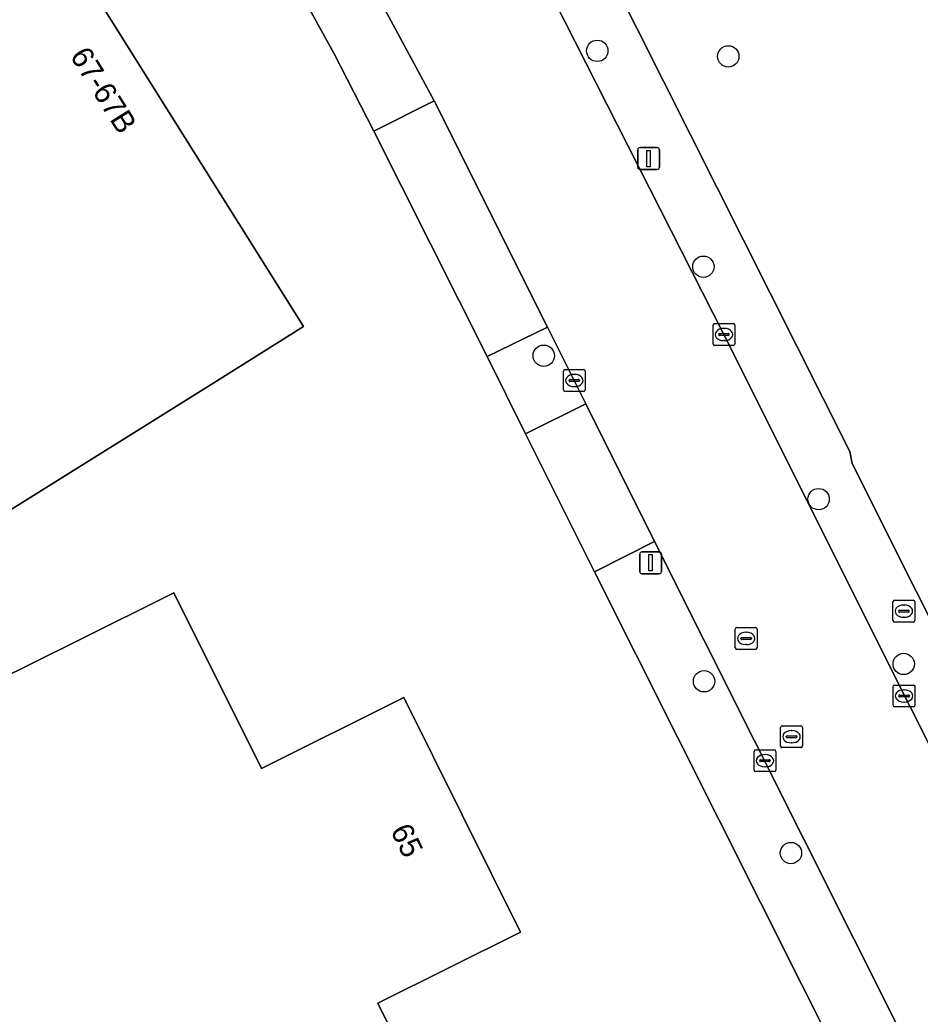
# Model space of a CAD drawing. Extents: x 158455 to 159797, y 387218 to 388672.
# Drawn here: x 158895.54 to 158936.77, y 387610.64 to 387656.15 of the extents above; entities that cross this region are included whole.
import ezdxf

# ---------------------------------------------------------------- set-up
doc = ezdxf.new("R2010")
doc.units = 0
for name, color, linetype in [('IMGEO_Boom', 7, 'Continuous'), ('IMGEO_Brandkraan', 7, 'Continuous'), ('IMGEO_Erf', 7, 'Continuous'), ('IMGEO_Groenvoorziening', 7, 'Continuous'), ('IMGEO_Kolk', 7, 'Continuous'), ('IMGEO_Lichtmast', 7, 'Continuous'), ('IMGEO_Pand', 7, 'Continuous'), ('IMGEO_Pand_nummerreeks', 7, 'Continuous'), ('IMGEO_Rijbaan_lokaal_gesloten', 7, 'Continuous'), ('IMGEO_Rioolput', 7, 'Continuous'), ('IMGEO_Voetpad_open', 7, 'Continuous')]:
    doc.layers.add(name, color=color, linetype=linetype)

msp = doc.modelspace()

# ---------------------------------------------------------------- linework, layer by layer
at = {"layer": 'IMGEO_Boom'}
for centre in [(158921.984, 387654.736), (158927.986, 387654.482), (158926.848, 387644.852), (158919.537, 387640.778), (158932.124, 387634.213), (158936.021, 387626.668), (158926.88, 387625.877), (158930.855, 387618.013)]:
    msp.add_circle(centre, 0.489, dxfattribs=at)
at = {"layer": 'IMGEO_Brandkraan'}
for p, q in [((158935.605, 387629.586), (158936.457, 387629.586)), ((158935.53, 387628.66), (158935.53, 387629.512)), ((158935.789, 387629.08), (158935.789, 387629.092)), ((158935.832, 387629.129), (158936.23, 387629.129)), ((158936.018, 387629.366), (158936.043, 387629.366)), ((158936.273, 387629.092), (158936.273, 387629.08)), ((158936.531, 387629.512), (158936.531, 387628.66)), ((158936.227, 387629.043), (158935.829, 387629.043)), ((158936.041, 387628.806), (158936.016, 387628.806)), ((158936.457, 387628.586), (158935.605, 387628.586))]:
    msp.add_line(p, q, dxfattribs=at)
for points in [[(158935.605, 387629.586), (158936.457, 387629.586)], [(158935.53, 387628.66), (158935.53, 387629.512)], [(158936.531, 387629.512), (158936.531, 387628.66)], [(158936.457, 387628.586), (158935.605, 387628.586)]]:
    msp.add_lwpolyline(points, dxfattribs=at)
for centre, radius, start, end in [((158935.607, 387629.51), 0.0765, 91.552, 178.448), ((158935.607, 387629.51), 0.0765, 91.552, 178.448), ((158936.455, 387629.51), 0.0765, 1.552, 88.448), ((158936.455, 387629.51), 0.0765, 1.552, 88.448), ((158935.829, 387629.089), 0.0403, 85.8775, 175.7526), ((158935.826, 387629.079), 0.0366, 178.938, 274.7102), ((158936.23, 387629.086), 0.043, 264.8664, 352.4533), ((158936.234, 387629.091), 0.0386, 1.7309, 96.639), ((158935.607, 387628.662), 0.0765, 181.552, 268.448), ((158935.607, 387628.662), 0.0765, 181.552, 268.448), ((158936.455, 387628.662), 0.0765, 271.552, 358.448), ((158936.455, 387628.662), 0.0765, 271.552, 358.448)]:
    msp.add_arc(centre, radius, start, end, dxfattribs=at)
for centre, major_axis, ratio, start_param, end_param in [((158936.017, 387629.086), (-0.387, 0.002), 0.722429, 4.712389, 7.853982), ((158936.042, 387629.086), (-0.39, 0.002), 0.717154, 1.570796, 4.712389)]:
    msp.add_ellipse(centre, major_axis=major_axis, ratio=ratio, start_param=start_param, end_param=end_param, dxfattribs=at)
at = {"layer": 'IMGEO_Erf'}
for points in [[(158943.323, 387588.149), (158935.963, 387602.773), (158933.26, 387608.176), (158921.856, 387630.891), (158918.695, 387637.196), (158916.94, 387640.737), (158911.753, 387651.052), (158909.925, 387654.635), (158906.951, 387660.034), (158903.404, 387666.016), (158897.586, 387674.782)], [(158895.119, 387663.494), (158908.535, 387642.117), (158904.295, 387639.469), (158885.82, 387627.929), (158888.801, 387623.081), (158898.121, 387627.704), (158902.597, 387629.931), (158906.604, 387621.885), (158913.12, 387625.134), (158918.477, 387614.393), (158911.935, 387611.134), (158915.862, 387603.234), (158911.387, 387601.004), (158897.995, 387594.33), (158886.575, 387615.835), (158883.635, 387620.442), (158869.854, 387642.432), (158867.642, 387645.962), (158864.987, 387650.199), (158869.238, 387652.895), (158867.621, 387655.417), (158878.047, 387661.941)]]:
    msp.add_lwpolyline(points, dxfattribs=at)
at = {"layer": 'IMGEO_Groenvoorziening'}
msp.add_lwpolyline([(158908.159, 387682.093), (158913.743, 387673.679), (158916.645, 387668.895), (158919.566, 387663.783), (158922.608, 387658.152), (158933.55, 387636.401), (158933.668, 387635.841), (158945.355, 387612.535), (158951.609, 387615.644), (158951.046, 387616.798), (158948.883, 387621.227), (158946.279, 387626.609), (158944.377, 387630.625), (159006.332, 387661.445), (159008.345, 387657.448), (159012.199, 387659.391)], dxfattribs=at)
at = {"layer": 'IMGEO_Kolk'}
for p, q in [((158927.288, 387641.325), (158927.288, 387642.177)), ((158927.363, 387642.251), (158928.215, 387642.251)), ((158927.776, 387642.031), (158927.801, 387642.031)), ((158928.289, 387642.177), (158928.289, 387641.325)), ((158927.547, 387641.745), (158927.547, 387641.757)), ((158927.985, 387641.708), (158927.587, 387641.708)), ((158927.59, 387641.794), (158927.988, 387641.794)), ((158927.799, 387641.471), (158927.774, 387641.471)), ((158928.031, 387641.757), (158928.031, 387641.745)), ((158928.215, 387641.251), (158927.363, 387641.251)), ((158920.434, 387639.217), (158920.434, 387640.069)), ((158920.509, 387640.143), (158921.361, 387640.143)), ((158921.435, 387640.069), (158921.435, 387639.217)), ((158920.693, 387639.637), (158920.693, 387639.649)), ((158921.131, 387639.6), (158920.733, 387639.6)), ((158920.736, 387639.686), (158921.134, 387639.686)), ((158920.922, 387639.923), (158920.947, 387639.923)), ((158921.177, 387639.649), (158921.177, 387639.637)), ((158921.361, 387639.143), (158920.509, 387639.143)), ((158920.945, 387639.363), (158920.92, 387639.363)), ((158935.538, 387624.778), (158935.538, 387625.63)), ((158935.613, 387625.704), (158936.465, 387625.704)), ((158936.026, 387625.484), (158936.051, 387625.484)), ((158936.539, 387625.63), (158936.539, 387624.778)), ((158935.797, 387625.198), (158935.797, 387625.21)), ((158936.235, 387625.161), (158935.837, 387625.161)), ((158935.84, 387625.247), (158936.238, 387625.247)), ((158936.281, 387625.21), (158936.281, 387625.198)), ((158936.465, 387624.704), (158935.613, 387624.704)), ((158936.049, 387624.924), (158936.024, 387624.924)), ((158929.242, 387622.739), (158930.094, 387622.739)), ((158929.167, 387621.813), (158929.167, 387622.665)), ((158929.426, 387622.233), (158929.426, 387622.245)), ((158929.469, 387622.282), (158929.867, 387622.282)), ((158929.655, 387622.519), (158929.68, 387622.519)), ((158929.91, 387622.245), (158929.91, 387622.233)), ((158930.168, 387622.665), (158930.168, 387621.813)), ((158929.864, 387622.196), (158929.466, 387622.196)), ((158929.678, 387621.959), (158929.653, 387621.959)), ((158930.094, 387621.739), (158929.242, 387621.739))]:
    msp.add_line(p, q, dxfattribs=at)
for points in [[(158927.288, 387641.325), (158927.288, 387642.177)], [(158927.363, 387642.251), (158928.215, 387642.251)], [(158928.289, 387642.177), (158928.289, 387641.325)], [(158928.215, 387641.251), (158927.363, 387641.251)], [(158920.434, 387639.217), (158920.434, 387640.069)], [(158920.509, 387640.143), (158921.361, 387640.143)], [(158921.435, 387640.069), (158921.435, 387639.217)], [(158921.361, 387639.143), (158920.509, 387639.143)], [(158935.538, 387624.778), (158935.538, 387625.63)], [(158935.613, 387625.704), (158936.465, 387625.704)], [(158936.539, 387625.63), (158936.539, 387624.778)], [(158936.465, 387624.704), (158935.613, 387624.704)], [(158929.242, 387622.739), (158930.094, 387622.739)], [(158929.167, 387621.813), (158929.167, 387622.665)], [(158930.168, 387622.665), (158930.168, 387621.813)], [(158930.094, 387621.739), (158929.242, 387621.739)]]:
    msp.add_lwpolyline(points, dxfattribs=at)
for centre, radius, start, end in [((158927.365, 387642.175), 0.0765, 91.552, 178.448), ((158927.365, 387642.175), 0.0765, 91.552, 178.448), ((158928.213, 387642.175), 0.0765, 1.552, 88.448), ((158928.213, 387642.175), 0.0765, 1.552, 88.448), ((158927.587, 387641.754), 0.0403, 85.8775, 175.7526), ((158927.584, 387641.744), 0.0366, 178.938, 274.7102), ((158927.988, 387641.751), 0.043, 264.8664, 352.4533), ((158927.992, 387641.756), 0.0386, 1.7309, 96.639), ((158927.365, 387641.327), 0.0765, 181.552, 268.448), ((158927.365, 387641.327), 0.0765, 181.552, 268.448), ((158928.213, 387641.327), 0.0765, 271.552, 358.448), ((158928.213, 387641.327), 0.0765, 271.552, 358.448), ((158920.511, 387640.067), 0.0765, 91.552, 178.448), ((158920.511, 387640.067), 0.0765, 91.552, 178.448), ((158921.359, 387640.067), 0.0765, 1.552, 88.448), ((158921.359, 387640.067), 0.0765, 1.552, 88.448), ((158920.733, 387639.646), 0.0403, 85.8775, 175.7526), ((158920.73, 387639.636), 0.0366, 178.938, 274.7102), ((158921.134, 387639.643), 0.043, 264.8664, 352.4533), ((158921.138, 387639.648), 0.0386, 1.7309, 96.639), ((158920.511, 387639.219), 0.0765, 181.552, 268.448), ((158920.511, 387639.219), 0.0765, 181.552, 268.448), ((158921.359, 387639.219), 0.0765, 271.552, 358.448), ((158921.359, 387639.219), 0.0765, 271.552, 358.448), ((158935.615, 387625.628), 0.0765, 91.552, 178.448), ((158935.615, 387625.628), 0.0765, 91.552, 178.448), ((158936.463, 387625.628), 0.0765, 1.552, 88.448), ((158936.463, 387625.628), 0.0765, 1.552, 88.448), ((158935.837, 387625.207), 0.0403, 85.8775, 175.7526), ((158935.834, 387625.197), 0.0366, 178.938, 274.7102), ((158936.238, 387625.204), 0.043, 264.8664, 352.4533), ((158936.242, 387625.209), 0.0386, 1.7309, 96.639), ((158935.615, 387624.78), 0.0765, 181.552, 268.448), ((158935.615, 387624.78), 0.0765, 181.552, 268.448), ((158936.463, 387624.78), 0.0765, 271.552, 358.448), ((158936.463, 387624.78), 0.0765, 271.552, 358.448), ((158929.244, 387622.663), 0.0765, 91.552, 178.448), ((158929.244, 387622.663), 0.0765, 91.552, 178.448), ((158930.092, 387622.663), 0.0765, 1.552, 88.448), ((158930.092, 387622.663), 0.0765, 1.552, 88.448), ((158929.466, 387622.242), 0.0403, 85.8775, 175.7526), ((158929.871, 387622.244), 0.0386, 1.7309, 96.639), ((158929.244, 387621.815), 0.0765, 181.552, 268.448), ((158929.244, 387621.815), 0.0765, 181.552, 268.448), ((158929.463, 387622.232), 0.0366, 178.938, 274.7102), ((158929.867, 387622.239), 0.043, 264.8664, 352.4533), ((158930.092, 387621.815), 0.0765, 271.552, 358.448), ((158930.092, 387621.815), 0.0765, 271.552, 358.448)]:
    msp.add_arc(centre, radius, start, end, dxfattribs=at)
for centre, major_axis, ratio, start_param, end_param in [((158927.775, 387641.751), (-0.387, 0.002), 0.722429, 4.712389, 7.853982), ((158927.8, 387641.751), (-0.39, 0.002), 0.717154, 1.570796, 4.712389), ((158920.921, 387639.643), (-0.387, 0.002), 0.722429, 4.712389, 7.853982), ((158920.946, 387639.643), (-0.39, 0.002), 0.717154, 1.570796, 4.712389), ((158936.025, 387625.204), (-0.387, 0.002), 0.722429, 4.712389, 7.853982), ((158936.05, 387625.204), (-0.39, 0.002), 0.717154, 1.570796, 4.712389), ((158929.654, 387622.239), (-0.387, 0.002), 0.722429, 4.712389, 7.853982), ((158929.679, 387622.239), (-0.39, 0.002), 0.717154, 1.570796, 4.712389)]:
    msp.add_ellipse(centre, major_axis=major_axis, ratio=ratio, start_param=start_param, end_param=end_param, dxfattribs=at)
at = {"layer": 'IMGEO_Lichtmast'}
for p, q in [((158923.844, 387649.406), (158923.844, 387650.206)), ((158923.844, 387650.206), (158923.844, 387649.406)), ((158923.944, 387650.306), (158924.734, 387650.306)), ((158924.734, 387650.306), (158923.944, 387650.306)), ((158924.834, 387650.206), (158924.834, 387649.406)), ((158924.834, 387649.406), (158924.834, 387650.206)), ((158924.734, 387649.306), (158923.944, 387649.306)), ((158923.944, 387649.306), (158924.734, 387649.306)), ((158923.931, 387630.9), (158923.931, 387631.7)), ((158923.931, 387631.7), (158923.931, 387630.9)), ((158924.031, 387631.8), (158924.821, 387631.8)), ((158924.821, 387631.8), (158924.031, 387631.8)), ((158924.921, 387631.7), (158924.921, 387630.9)), ((158924.921, 387630.9), (158924.921, 387631.7)), ((158924.821, 387630.8), (158924.031, 387630.8)), ((158924.031, 387630.8), (158924.821, 387630.8))]:
    msp.add_line(p, q, dxfattribs=at)
for points in [[(158924.264, 387650.181), (158924.414, 387650.181), (158924.414, 387649.431), (158924.264, 387649.431), (158924.264, 387650.181)], [(158924.351, 387631.675), (158924.501, 387631.675), (158924.501, 387630.925), (158924.351, 387630.925), (158924.351, 387631.675)]]:
    msp.add_lwpolyline(points, dxfattribs=at)
for centre, start, end in [((158923.944, 387650.206), 90, 180), ((158923.944, 387650.206), 90, 180), ((158924.734, 387650.206), 0, 90), ((158924.734, 387650.206), 360, 90), ((158923.944, 387649.406), 180, 270), ((158923.944, 387649.406), 180, 270), ((158924.734, 387649.406), 270, 0), ((158924.734, 387649.406), 270, 0), ((158924.031, 387631.7), 90, 180), ((158924.031, 387631.7), 90, 180), ((158924.821, 387631.7), 0, 90), ((158924.821, 387631.7), 360, 90), ((158924.031, 387630.9), 180, 270), ((158924.031, 387630.9), 180, 270), ((158924.821, 387630.9), 270, 0), ((158924.821, 387630.9), 270, 0)]:
    msp.add_arc(centre, 0.1, start, end, dxfattribs=at)
at = {"layer": 'IMGEO_Pand'}
for points in [[(158895.119, 387663.494), (158896.065, 387664.099), (158894.225, 387667.08), (158888.459, 387668.453), (158883.343, 387665.253), (158878.323, 387662.112), (158877.512, 387663.377), (158877.239, 387663.227), (158878.047, 387661.941), (158867.621, 387655.417), (158869.238, 387652.895), (158864.987, 387650.199), (158867.642, 387645.962), (158869.854, 387642.432), (158883.635, 387620.442), (158888.801, 387623.081), (158885.82, 387627.929), (158904.295, 387639.469), (158908.535, 387642.117)], [(158883.635, 387620.442), (158886.575, 387615.835), (158897.995, 387594.33), (158911.387, 387601.004), (158915.862, 387603.234), (158911.935, 387611.134), (158918.477, 387614.393), (158913.12, 387625.134), (158906.604, 387621.885), (158902.597, 387629.931), (158898.121, 387627.704), (158888.801, 387623.081)]]:
    msp.add_lwpolyline(points, close=True, dxfattribs=at)
at = {"layer": 'IMGEO_Rijbaan_lokaal_gesloten'}
for points in [[(158952.06, 387593.215), (158951.418, 387594.547), (158944.884, 387607.596), (158927.789, 387641.751), (158919.992, 387657.088), (158917.009, 387662.578), (158914.339, 387667.291), (158911.457, 387672.114), (158905.886, 387680.514)], [(158900.847, 387675.374), (158901.529, 387674.337), (158904.447, 387669.973), (158907.576, 387664.901), (158911.705, 387657.663), (158914.511, 387652.445), (158919.71, 387642.093), (158921.465, 387638.578), (158924.613, 387632.28), (158936.019, 387609.551), (158938.739, 387604.133), (158945.43, 387590.82), (158945.878, 387589.923)]]:
    msp.add_lwpolyline(points, dxfattribs=at)
at = {"layer": 'IMGEO_Rioolput'}
for p, q in [((158928.305, 387627.411), (158928.305, 387628.263)), ((158928.38, 387628.337), (158929.232, 387628.337)), ((158929.306, 387628.263), (158929.306, 387627.411)), ((158928.564, 387627.831), (158928.564, 387627.843)), ((158929.002, 387627.794), (158928.604, 387627.794)), ((158928.607, 387627.88), (158929.005, 387627.88)), ((158928.793, 387628.117), (158928.818, 387628.117)), ((158929.048, 387627.843), (158929.048, 387627.831)), ((158929.232, 387627.337), (158928.38, 387627.337)), ((158928.816, 387627.557), (158928.791, 387627.557)), ((158930.384, 387622.911), (158930.384, 387623.763)), ((158930.459, 387623.837), (158931.311, 387623.837)), ((158930.872, 387623.617), (158930.897, 387623.617)), ((158931.385, 387623.763), (158931.385, 387622.911)), ((158930.643, 387623.331), (158930.643, 387623.343)), ((158931.081, 387623.294), (158930.683, 387623.294)), ((158930.686, 387623.38), (158931.084, 387623.38)), ((158931.127, 387623.343), (158931.127, 387623.331)), ((158931.311, 387622.837), (158930.459, 387622.837)), ((158930.895, 387623.057), (158930.87, 387623.057))]:
    msp.add_line(p, q, dxfattribs=at)
for points in [[(158928.305, 387627.411), (158928.305, 387628.263)], [(158928.38, 387628.337), (158929.232, 387628.337)], [(158929.306, 387628.263), (158929.306, 387627.411)], [(158929.232, 387627.337), (158928.38, 387627.337)], [(158930.384, 387622.911), (158930.384, 387623.763)], [(158930.459, 387623.837), (158931.311, 387623.837)], [(158931.385, 387623.763), (158931.385, 387622.911)], [(158931.311, 387622.837), (158930.459, 387622.837)]]:
    msp.add_lwpolyline(points, dxfattribs=at)
for centre, radius, start, end in [((158928.382, 387628.261), 0.0765, 91.552, 178.448), ((158928.382, 387628.261), 0.0765, 91.552, 178.448), ((158929.23, 387628.261), 0.0765, 1.552, 88.448), ((158929.23, 387628.261), 0.0765, 1.552, 88.448), ((158928.604, 387627.84), 0.0403, 85.8775, 175.7526), ((158928.601, 387627.83), 0.0366, 178.938, 274.7102), ((158929.005, 387627.837), 0.043, 264.8664, 352.4533), ((158929.009, 387627.842), 0.0386, 1.7309, 96.639), ((158928.382, 387627.413), 0.0765, 181.552, 268.448), ((158928.382, 387627.413), 0.0765, 181.552, 268.448), ((158929.23, 387627.413), 0.0765, 271.552, 358.448), ((158929.23, 387627.413), 0.0765, 271.552, 358.448), ((158930.461, 387623.761), 0.0765, 91.552, 178.448), ((158930.461, 387623.761), 0.0765, 91.552, 178.448), ((158931.309, 387623.761), 0.0765, 1.552, 88.448), ((158931.309, 387623.761), 0.0765, 1.552, 88.448), ((158930.683, 387623.34), 0.0403, 85.8775, 175.7526), ((158930.68, 387623.33), 0.0366, 178.938, 274.7102), ((158931.084, 387623.337), 0.043, 264.8664, 352.4533), ((158931.088, 387623.342), 0.0386, 1.7309, 96.639), ((158930.461, 387622.913), 0.0765, 181.552, 268.448), ((158930.461, 387622.913), 0.0765, 181.552, 268.448), ((158931.309, 387622.913), 0.0765, 271.552, 358.448), ((158931.309, 387622.913), 0.0765, 271.552, 358.448)]:
    msp.add_arc(centre, radius, start, end, dxfattribs=at)
for centre, major_axis, ratio, start_param, end_param in [((158928.792, 387627.837), (-0.387, 0.002), 0.722429, 4.712389, 7.853982), ((158928.817, 387627.837), (-0.39, 0.002), 0.717154, 1.570796, 4.712389), ((158930.871, 387623.337), (-0.387, 0.002), 0.722429, 4.712389, 7.853982), ((158930.896, 387623.337), (-0.39, 0.002), 0.717154, 1.570796, 4.712389)]:
    msp.add_ellipse(centre, major_axis=major_axis, ratio=ratio, start_param=start_param, end_param=end_param, dxfattribs=at)
at = {"layer": 'IMGEO_Voetpad_open'}
for points in [[(158933.55, 387636.401), (158922.608, 387658.152), (158919.566, 387663.783), (158916.645, 387668.895), (158913.743, 387673.679), (158908.159, 387682.093)], [(158906.826, 387681.188), (158905.886, 387680.514), (158911.457, 387672.114), (158914.339, 387667.291), (158917.009, 387662.578), (158919.992, 387657.088), (158927.789, 387641.751), (158944.884, 387607.596), (158945.355, 387607.843), (158951.877, 387594.81), (158952.504, 387595.008), (158953.469, 387593.046)], [(158897.586, 387674.782), (158903.404, 387666.016), (158906.951, 387660.034), (158909.925, 387654.635), (158911.753, 387651.052), (158914.511, 387652.445), (158911.705, 387657.663)], [(158948.418, 387573.599), (158949.423, 387571.741), (158957.461, 387576.099), (158957.303, 387576.367), (158962.13, 387578.938), (158947.594, 387608.591), (158947.378, 387608.501), (158945.355, 387612.535), (158933.668, 387635.841), (158933.55, 387636.401)]]:
    msp.add_lwpolyline(points, dxfattribs=at)
for points in [[(158916.94, 387640.737), (158919.71, 387642.093), (158914.511, 387652.445), (158911.753, 387651.052)], [(158921.465, 387638.578), (158919.71, 387642.093), (158916.94, 387640.737), (158918.695, 387637.196)], [(158921.856, 387630.891), (158924.613, 387632.28), (158921.465, 387638.578), (158918.695, 387637.196)], [(158933.26, 387608.176), (158936.019, 387609.551), (158924.613, 387632.28), (158921.856, 387630.891)]]:
    msp.add_lwpolyline(points, close=True, dxfattribs=at)

# ---------------------------------------------------------------- texts
at = {"layer": 'IMGEO_Pand_nummerreeks'}
for s, rotation, p in [('67-67B', 302.1141, (158897.81, 387654.503)), ('65', 296.5074, (158912.494, 387619.039))]:
    msp.add_text(s, height=1, rotation=rotation, dxfattribs=at).set_placement(p)

doc.saveas('drawing.dxf')
